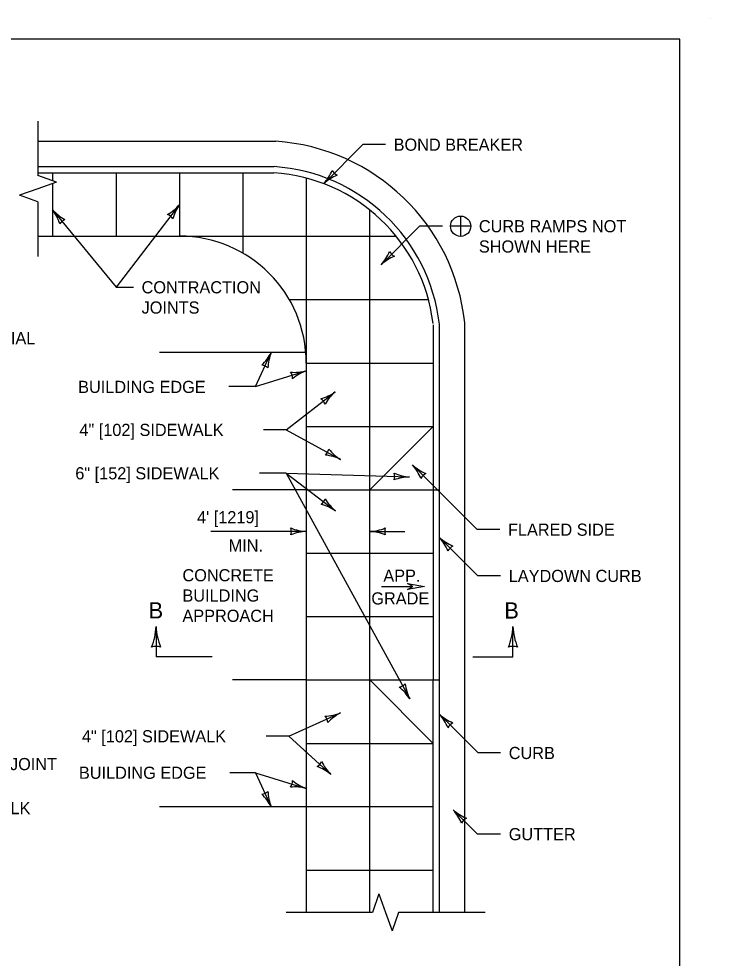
# Model space of a CAD drawing. Extents: x 49987.9 to 50021, y 49987.6 to 50011.4.
# Drawn here: x 50005.356 to 50008.765, y 50006.728 to 50011.363 of the extents above; entities that cross this region are included whole.
import ezdxf

# ---------------------------------------------------------------- set-up
doc = ezdxf.new("R2010")
doc.units = 0
for name, color, linetype in [('Level 1', 7, 'Continuous'), ('Level 2', 7, 'Continuous'), ('Level 3', 7, 'Continuous'), ('Level 4', 7, 'Continuous'), ('Level 6', 7, 'Continuous'), ('Level 7', 7, 'Continuous')]:
    doc.layers.add(name, color=color, linetype=linetype)

msp = doc.modelspace()

# ---------------------------------------------------------------- linework, layer by layer
at = {"layer": 'Level 1'}
for p, q in [((50008.7646, 50011.3628), (50008.7646, 50011.3628)), ((50005.45, 50010.7584), (50006.6236, 50010.7584)), ((50005.45, 50010.6334), (50006.6151, 50010.6334)), ((50005.45, 50010.6034), (50006.6131, 50010.6034)), ((50005.5224, 50010.6034), (50005.5224, 50010.5635)), ((50005.8354, 50010.6034), (50005.8354, 50010.2904)), ((50006.1484, 50010.6034), (50006.1484, 50010.2904)), ((50006.4614, 50010.206), (50006.4614, 50010.6034)), ((50006.7734, 50010.5769), (50006.7734, 50009.039)), ((50005.5224, 50010.5501), (50005.5224, 50010.2904)), ((50007.0864, 50009.039), (50007.0864, 50010.419)), ((50005.45, 50010.2904), (50007.2157, 50010.2904)), ((50006.6895, 50009.9774), (50007.3756, 50009.9774)), ((50007.3994, 50009.8534), (50007.3994, 50009.039)), ((50007.4294, 50009.039), (50007.4294, 50009.8566)), ((50007.5544, 50006.9539), (50007.5544, 50009.8628)), ((50006.7734, 50009.716), (50006.0499, 50009.716)), ((50006.7734, 50009.716), (50006.7734, 50007.4749)), ((50006.7734, 50009.6644), (50007.3994, 50009.6644)), ((50006.7734, 50009.3517), (50007.3994, 50009.3517)), ((50007.0864, 50009.039), (50007.3994, 50009.3517)), ((50006.7744, 50009.039), (50006.4099, 50009.039)), ((50006.7734, 50009.039), (50007.0864, 50009.039)), ((50007.0864, 50008.1009), (50007.0864, 50009.039)), ((50007.0864, 50009.039), (50007.4294, 50009.039)), ((50007.3994, 50009.039), (50007.4294, 50009.039)), ((50007.3994, 50009.039), (50007.3994, 50008.1009)), ((50006.7734, 50008.7263), (50007.3994, 50008.7263)), ((50006.7734, 50008.4136), (50007.3994, 50008.4136)), ((50006.7744, 50008.1009), (50006.4099, 50008.1009)), ((50006.7734, 50008.1009), (50006.7734, 50006.9539)), ((50006.7734, 50008.1009), (50007.0864, 50008.1009)), ((50007.0864, 50006.9539), (50007.0864, 50008.1009)), ((50007.0864, 50008.1009), (50007.3994, 50007.7872)), ((50007.0864, 50008.1009), (50007.4294, 50008.1009)), ((50007.3994, 50008.1014), (50007.4294, 50008.1014)), ((50007.3994, 50006.9539), (50007.3994, 50008.1009)), ((50007.4294, 50006.9539), (50007.4294, 50008.1014)), ((50006.7734, 50007.7872), (50007.3994, 50007.7872)), ((50007.3994, 50007.4749), (50006.0499, 50007.4749)), ((50006.7734, 50007.1618), (50007.3994, 50007.1618))]:
    msp.add_line(p, q, dxfattribs=at)
msp.add_lwpolyline([(50008.6146, 50011.2628), (50000.3356, 50011.2628), (50000.3356, 50000.0624), (50008.6146, 50000.0624)], close=True, dxfattribs=at)
for centre, radius, start, end in [((50006.5557, 50009.7563), 1.0044, 6.0866, 86.1225), ((50006.5556, 50009.7558), 0.8796, 6.5753, 86.1225), ((50006.5556, 50009.756), 0.8493, 7.0385, 86.1019), ((50006.1474, 50009.6644), 0.626, 0, 89.9085)]:
    msp.add_arc(centre, radius, start, end, dxfattribs=at)
at = {"layer": 'Level 2'}
for p, q in [((50007.5342, 50010.3893), (50007.5342, 50010.2893)), ((50007.5842, 50010.3393), (50007.4842, 50010.3393))]:
    msp.add_line(p, q, dxfattribs=at)
msp.add_circle((50007.5342, 50010.3393), 0.05, dxfattribs=at)
at = {"layer": 'Level 3'}
for p, q in [((50006.8594, 50010.5492), (50007.052, 50010.7418)), ((50007.164, 50010.7418), (50007.052, 50010.7418)), ((50006.1484, 50010.4469), (50005.8354, 50010.038)), ((50005.5224, 50010.4203), (50005.8354, 50010.038)), ((50007.1421, 50010.1492), (50007.3322, 50010.3393)), ((50007.4442, 50010.3393), (50007.3322, 50010.3393)), ((50005.8354, 50010.038), (50005.9213, 50010.038)), ((50006.5228, 50009.5483), (50006.6008, 50009.716)), ((50006.5228, 50009.5483), (50006.7734, 50009.6256)), ((50006.5228, 50009.5483), (50006.3922, 50009.5483)), ((50006.6748, 50009.3343), (50006.9155, 50009.5216)), ((50006.6748, 50009.3343), (50006.5628, 50009.3343)), ((50006.6748, 50009.3343), (50006.9427, 50009.1887)), ((50007.2962, 50009.1616), (50007.6158, 50008.8421)), ((50006.6748, 50009.1203), (50006.5425, 50009.1203)), ((50006.6748, 50009.1203), (50006.9166, 50008.9345)), ((50006.6748, 50009.1203), (50007.2826, 50009.102)), ((50006.6749, 50009.1203), (50007.2832, 50008.0067)), ((50006.7734, 50008.8336), (50006.303, 50008.8336)), ((50007.0864, 50008.8336), (50007.2598, 50008.8336)), ((50007.7278, 50008.8421), (50007.6158, 50008.8421)), ((50007.4294, 50008.8039), (50007.6195, 50008.6138)), ((50007.7315, 50008.6138), (50007.6195, 50008.6138)), ((50006.6872, 50007.8226), (50006.9417, 50007.9376)), ((50007.4294, 50007.9318), (50007.621, 50007.7402)), ((50006.6872, 50007.8226), (50006.5752, 50007.8226)), ((50006.6872, 50007.8226), (50006.8938, 50007.6347)), ((50007.7315, 50007.7402), (50007.621, 50007.7402)), ((50006.5228, 50007.6427), (50006.3962, 50007.6427)), ((50006.5228, 50007.6427), (50006.7734, 50007.5654)), ((50006.5228, 50007.6427), (50006.6008, 50007.4749)), ((50007.4968, 50007.4603), (50007.6175, 50007.3396)), ((50007.7315, 50007.3396), (50007.6175, 50007.3396))]:
    msp.add_line(p, q, dxfattribs=at)
for centre, radius, start, end in [((50006.6867, 50010.7056), 0.233, 317.8273, 337.0772), ((50007.01, 50010.3856), 0.2223, 112.456, 132.6395), ((50006.95, 50010.6398), 0.0548, 207.1388, 242.8612), ((50005.9776, 50010.5892), 0.2223, 300.0231, 320.2066), ((50006.3402, 50010.3146), 0.233, 145.3944, 164.6443), ((50005.3447, 50010.2867), 0.2223, 16.7642, 36.9477), ((50005.6952, 50010.5766), 0.233, 222.1355, 241.3853), ((50006.0705, 50010.3451), 0.0548, 34.7059, 70.4283), ((50005.6036, 50010.3211), 0.0548, 111.447, 147.1694), ((50006.9694, 50010.3057), 0.233, 317.8273, 337.0772), ((50007.2327, 50010.2399), 0.0548, 207.1388, 242.8612), ((50007.2927, 50009.9857), 0.2223, 112.456, 132.6395), ((50006.4032, 50009.818), 0.2223, 312.5121, 332.6956), ((50006.8167, 50009.6283), 0.233, 157.8834, 177.1333), ((50006.5467, 50009.5997), 0.0548, 47.1949, 82.9173), ((50006.7167, 50009.8406), 0.2223, 264.5989, 284.7824), ((50006.6509, 50009.5878), 0.0548, 359.2817, 35.0041), ((50006.853, 50009.4066), 0.233, 109.9702, 129.22), ((50006.7863, 50009.7025), 0.2223, 285.3451, 305.5286), ((50007.0674, 50009.345), 0.233, 130.7164, 149.9662), ((50006.8143, 50009.4428), 0.0548, 20.0279, 55.7502), ((50006.8301, 50009.2499), 0.0548, 313.6133, 349.3356), ((50007.0568, 50009.3795), 0.2223, 218.9304, 239.114), ((50006.8417, 50008.9787), 0.233, 64.3017, 83.5516), ((50007.13, 50009.0086), 0.2259, 22.456, 42.6395), ((50007.4551, 50009.3371), 0.2367, 227.8273, 247.0772), ((50007.1544, 50009.1058), 0.0548, 340.4122, 16.1345), ((50007.2871, 50008.869), 0.233, 91.1006, 110.3505), ((50007.2984, 50009.3237), 0.2223, 245.7293, 265.9129), ((50007.3883, 50009.0695), 0.0557, 117.1388, 152.8612), ((50006.8149, 50009.0126), 0.0548, 304.6, 340.3224), ((50007.0592, 50009.1051), 0.2223, 209.9172, 230.1007), ((50006.7839, 50008.743), 0.233, 55.2885, 74.5384), ((50006.7826, 50009.0557), 0.2223, 247.456, 267.6395), ((50006.6452, 50008.8336), 0.0548, 342.1388, 17.8612), ((50006.7849, 50008.6009), 0.233, 92.8273, 112.0772), ((50007.0772, 50009.0557), 0.2223, 272.3605, 292.544), ((50007.0749, 50008.6009), 0.233, 67.9228, 87.1727), ((50007.2146, 50008.8336), 0.0548, 162.1388, 197.8612), ((50007.2632, 50008.6509), 0.2259, 22.456, 42.6395), ((50007.5883, 50008.9794), 0.2367, 227.8273, 247.0772), ((50007.5215, 50008.7118), 0.0557, 117.1388, 152.8612), ((50005.7367, 50008.3761), 0.2964, 337.456, 357.6395), ((50006.3432, 50008.3792), 0.3107, 182.8273, 202.0772), ((50007.4959, 50008.3758), 0.2964, 337.456, 357.6395), ((50008.1024, 50008.3789), 0.3107, 182.8273, 202.0772), ((50006.0329, 50008.193), 0.073, 72.1388, 107.8612), ((50007.7921, 50008.1927), 0.073, 72.1388, 107.8612), ((50007.2218, 50008.1192), 0.0548, 280.7852, 316.5075), ((50007.4826, 50008.1051), 0.2223, 186.1023, 206.2859), ((50007.0845, 50007.885), 0.233, 31.4736, 50.7235), ((50006.8586, 50008.1438), 0.2223, 271.7668, 291.9503), ((50007.048, 50007.7302), 0.233, 117.1381, 136.3879), ((50007.2632, 50007.7788), 0.2259, 22.456, 42.6395), ((50007.5883, 50008.1072), 0.2367, 227.8273, 247.0772), ((50006.8248, 50007.8848), 0.0548, 6.4496, 42.1719), ((50007.5215, 50007.8397), 0.0557, 117.1388, 152.8612), ((50006.7989, 50007.721), 0.0548, 299.8591, 335.5814), ((50007.05, 50007.7929), 0.2223, 205.1763, 225.3598), ((50006.7457, 50007.4548), 0.233, 50.5476, 69.7974), ((50006.6509, 50007.6032), 0.0548, 324.9959, 0.7183), ((50006.8476, 50007.775), 0.2223, 230.3131, 250.4966), ((50006.7158, 50007.3396), 0.233, 75.6844, 94.9343), ((50006.5468, 50007.5912), 0.0548, 277.0827, 312.8051), ((50006.3947, 50007.3663), 0.233, 27.7712, 47.0211), ((50006.8061, 50007.5603), 0.2223, 182.3999, 202.5834), ((50007.3333, 50007.3097), 0.2223, 22.456, 42.6395), ((50007.6532, 50007.633), 0.233, 227.8273, 247.0772), ((50007.5875, 50007.3696), 0.0548, 117.1388, 152.8612)]:
    msp.add_arc(centre, radius, start, end, dxfattribs=at)
at = {"layer": 'Level 4'}
msp.add_line((50007.4294, 50008.1014), (50007.4294, 50009.039), dxfattribs=at)
at = {"layer": 'Level 6'}
for p, q in [((50005.45, 50010.8584), (50005.45, 50010.5892)), ((50005.5414, 50010.5568), (50005.45, 50010.5892)), ((50005.45, 50010.5244), (50005.3586, 50010.492)), ((50005.5414, 50010.5568), (50005.45, 50010.5244)), ((50005.45, 50010.4596), (50005.3586, 50010.492)), ((50005.45, 50010.4596), (50005.45, 50010.1904)), ((50006.0329, 50008.3639), (50006.0329, 50008.2139)), ((50007.7921, 50008.2136), (50007.7921, 50008.3636)), ((50006.3099, 50008.2139), (50006.0329, 50008.2139)), ((50007.7921, 50008.2136), (50007.5944, 50008.2136)), ((50007.1315, 50007.0453), (50007.0991, 50006.9539)), ((50007.1315, 50007.0453), (50007.1639, 50006.9539)), ((50007.0991, 50006.9539), (50006.6734, 50006.9539)), ((50007.1639, 50006.9539), (50007.1963, 50006.8625)), ((50007.2287, 50006.9539), (50007.1963, 50006.8625)), ((50007.6544, 50006.9539), (50007.2287, 50006.9539))]:
    msp.add_line(p, q, dxfattribs=at)
at = {"layer": 'Level 7'}
msp.add_line((50007.1446, 50008.562), (50007.2981, 50008.562), dxfattribs=at)
msp.add_lwpolyline([(50007.2728, 50008.5766), (50007.3556, 50008.562), (50007.2728, 50008.5473), (50007.2981, 50008.562)], close=True, dxfattribs=at)

# ---------------------------------------------------------------- texts
at = {"layer": 'Level 2'}
for s, height, p in [('BOND BREAKER', 0.06, (50007.204, 50010.7118)), ('CURB RAMPS NOT', 0.06, (50007.6242, 50010.3093)), ('SHOWN HERE', 0.06, (50007.6242, 50010.2093)), ('CONTRACTION', 0.06, (50005.9613, 50010.008)), ('JOINTS', 0.06, (50005.9613, 50009.908)), ('OF ADJACENT MATERIAL', 0.06, (50004.4567, 50009.7571)), ('BUILDING EDGE', 0.06, (50005.6486, 50009.5165)), ('4" [102] SIDEWALK', 0.06, (50005.6548, 50009.3043)), ('6" [152] SIDEWALK', 0.06, (50005.6345, 50009.0903)), ("4' [1219] ", 0.06, (50006.2348, 50008.8736)), ('FLARED SIDE', 0.06, (50007.7678, 50008.8121)), ('MIN.', 0.06, (50006.3906, 50008.7336)), ('CONCRETE', 0.06, (50006.1628, 50008.5872)), ('APP.', 0.06, (50007.1532, 50008.5851)), ('LAYDOWN CURB', 0.06, (50007.7715, 50008.5838)), ('BUILDING', 0.06, (50006.1628, 50008.4872)), ('GRADE', 0.06, (50007.094, 50008.473)), ('B', 0.08, (50005.9963, 50008.4039)), ('APPROACH', 0.06, (50006.1628, 50008.3872)), ('B', 0.08, (50007.7499, 50008.4036)), ('4" [102] SIDEWALK', 0.06, (50005.6672, 50007.7926)), ('CURB', 0.06, (50007.7715, 50007.7102)), ('CONTRACTION JOINT', 0.06, (50004.702, 50007.6556)), ('BUILDING EDGE', 0.06, (50005.6525, 50007.6127)), ('4" [102] SIDEWALK', 0.06, (50004.7025, 50007.4383)), ('GUTTER', 0.06, (50007.7715, 50007.3096))]:
    msp.add_text(s, height=height, dxfattribs=at).set_placement(p)

doc.saveas('drawing.dxf')
